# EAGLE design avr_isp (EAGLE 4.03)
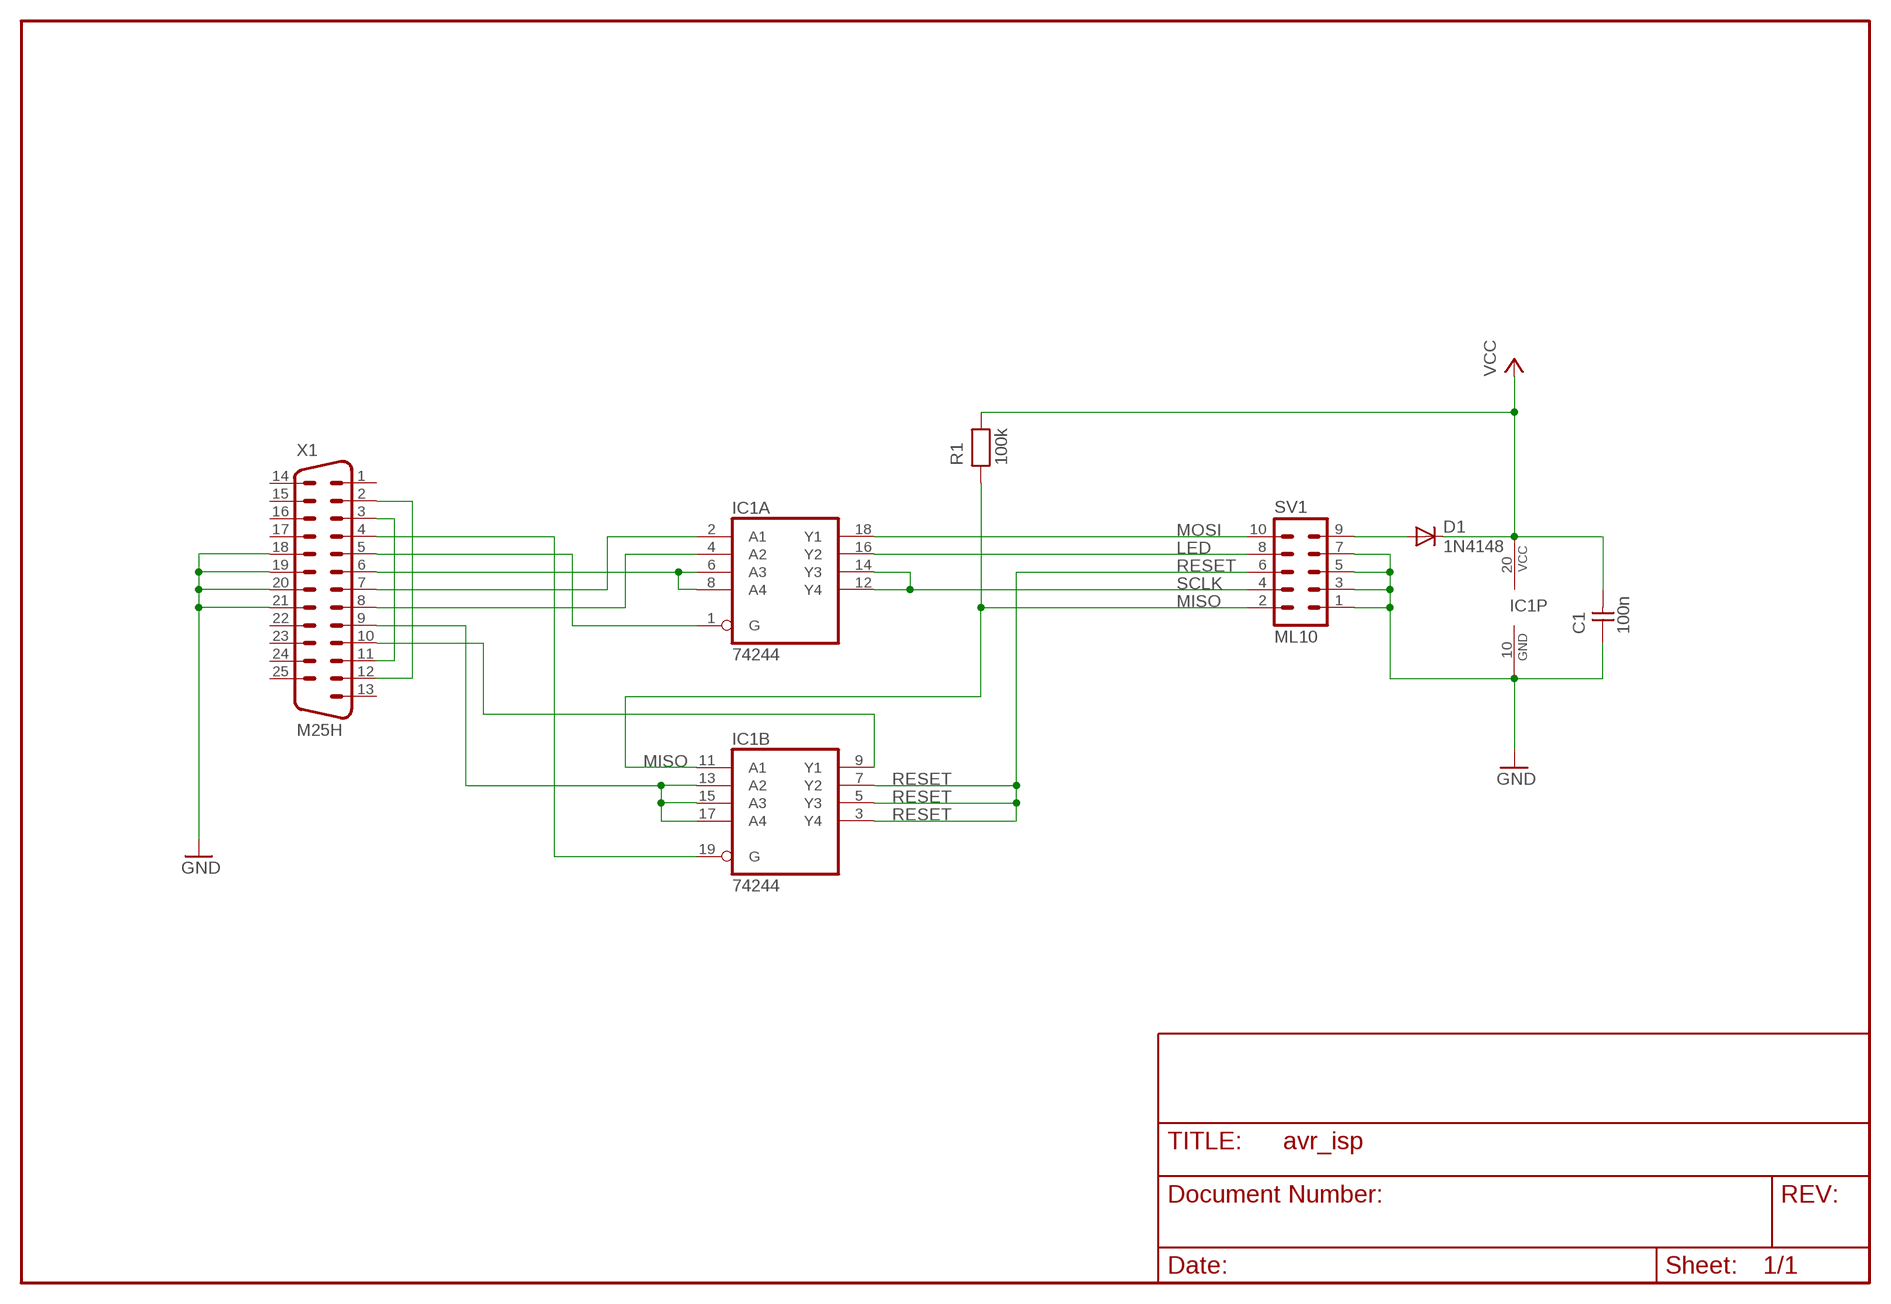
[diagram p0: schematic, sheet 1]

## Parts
C1  100n  CAPNP-2,5  [C-2,5]
D1  1N4148  [DO35-10]
IC1  74244  [DIL20]
R1  100k  RESEU-10  [R-10]
SV1  ML10  [ML10]
X1  M25H  [M25H]

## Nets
GND: C1.1 IC1.10(P:GND) SV1.1 SV1.3 SV1.5 SV1.7 X1.18 X1.19 X1.20 X1.21
LED: IC1.16(A:Y2) SV1.8
MISO: IC1.11(B:A1) R1.1 SV1.2
MOSI: IC1.18(A:Y1) SV1.10
N$5: IC1.1(A:G) X1.5
N$6: IC1.19(B:G) X1.4
N$7: IC1.2(A:A1) X1.7
N$8: IC1.4(A:A2) X1.8
N$9: X1.2 X1.12
N$10: X1.3 X1.11
N$12: IC1.9(B:Y1) X1.10
N$15: D1.A SV1.9
N$18: IC1.6(A:A3) IC1.8(A:A4) X1.6
N$20: IC1.13(B:A2) IC1.15(B:A3) IC1.17(B:A4) X1.9
RESET: IC1.3(B:Y4) IC1.5(B:Y3) IC1.7(B:Y2) SV1.6
SCLK: IC1.12(A:Y4) IC1.14(A:Y3) SV1.4
VCC: C1.2 D1.C IC1.20(P:VCC) R1.2
Unconnected: X1.1 X1.13 X1.14 X1.15 X1.16 X1.17 X1.22 X1.23 X1.24 X1.25

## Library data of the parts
C1 = discrete:CAPNP-2,5
D1 = diode:1N4148: DIODE
IC1 = 74xx:74244
R1 = discrete:RESEU-10
SV1 = con-ml:ML10: HARTING
X1 = subd:M25H

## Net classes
0 default: width 0.305 mm, clearance 0.406 mm

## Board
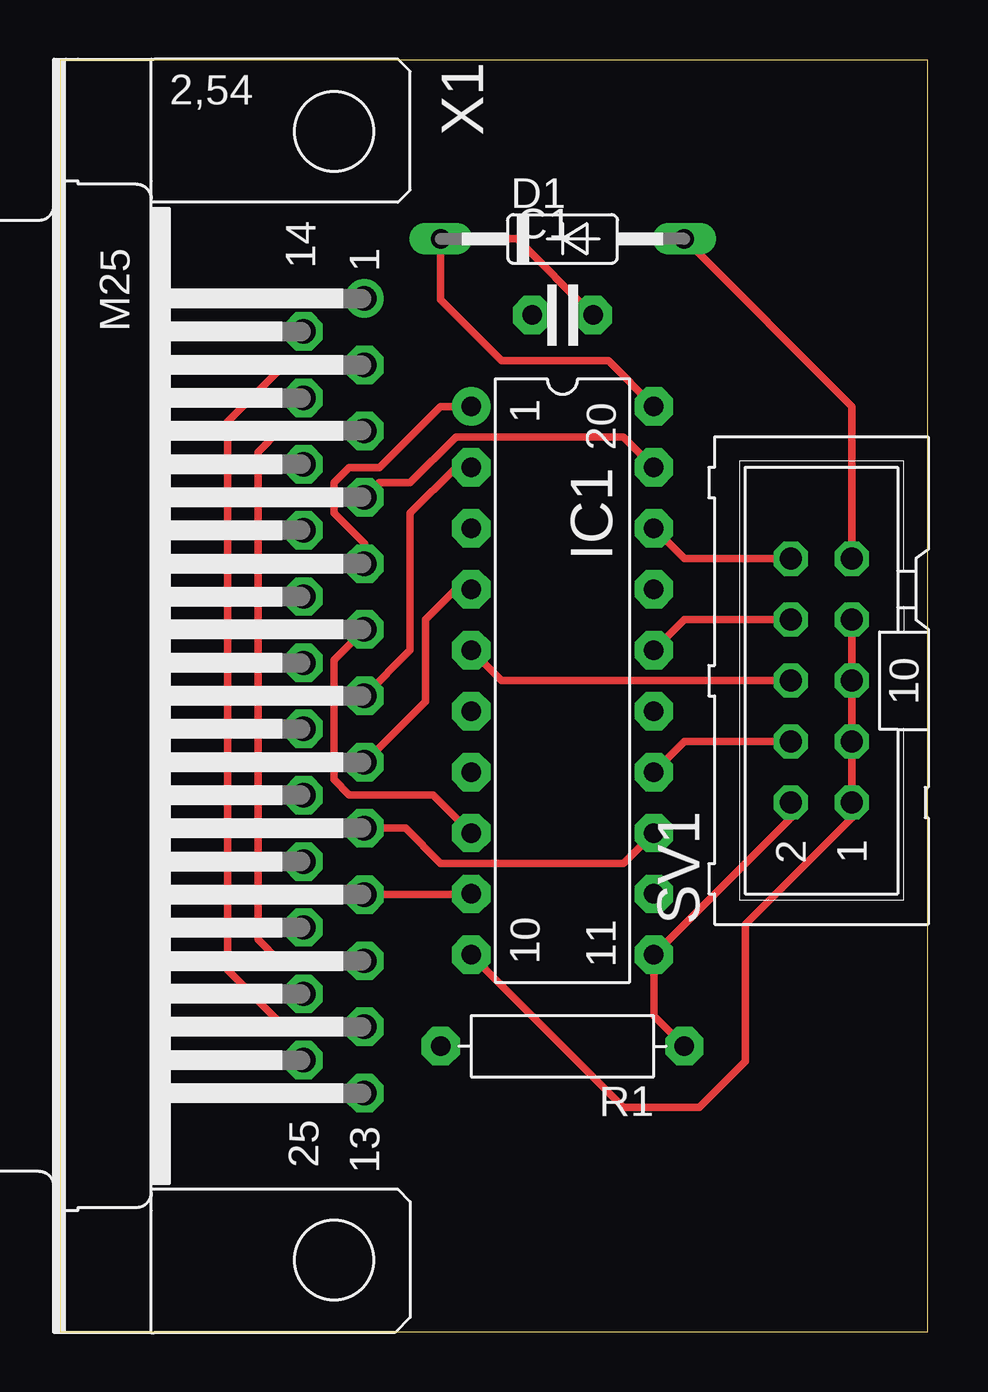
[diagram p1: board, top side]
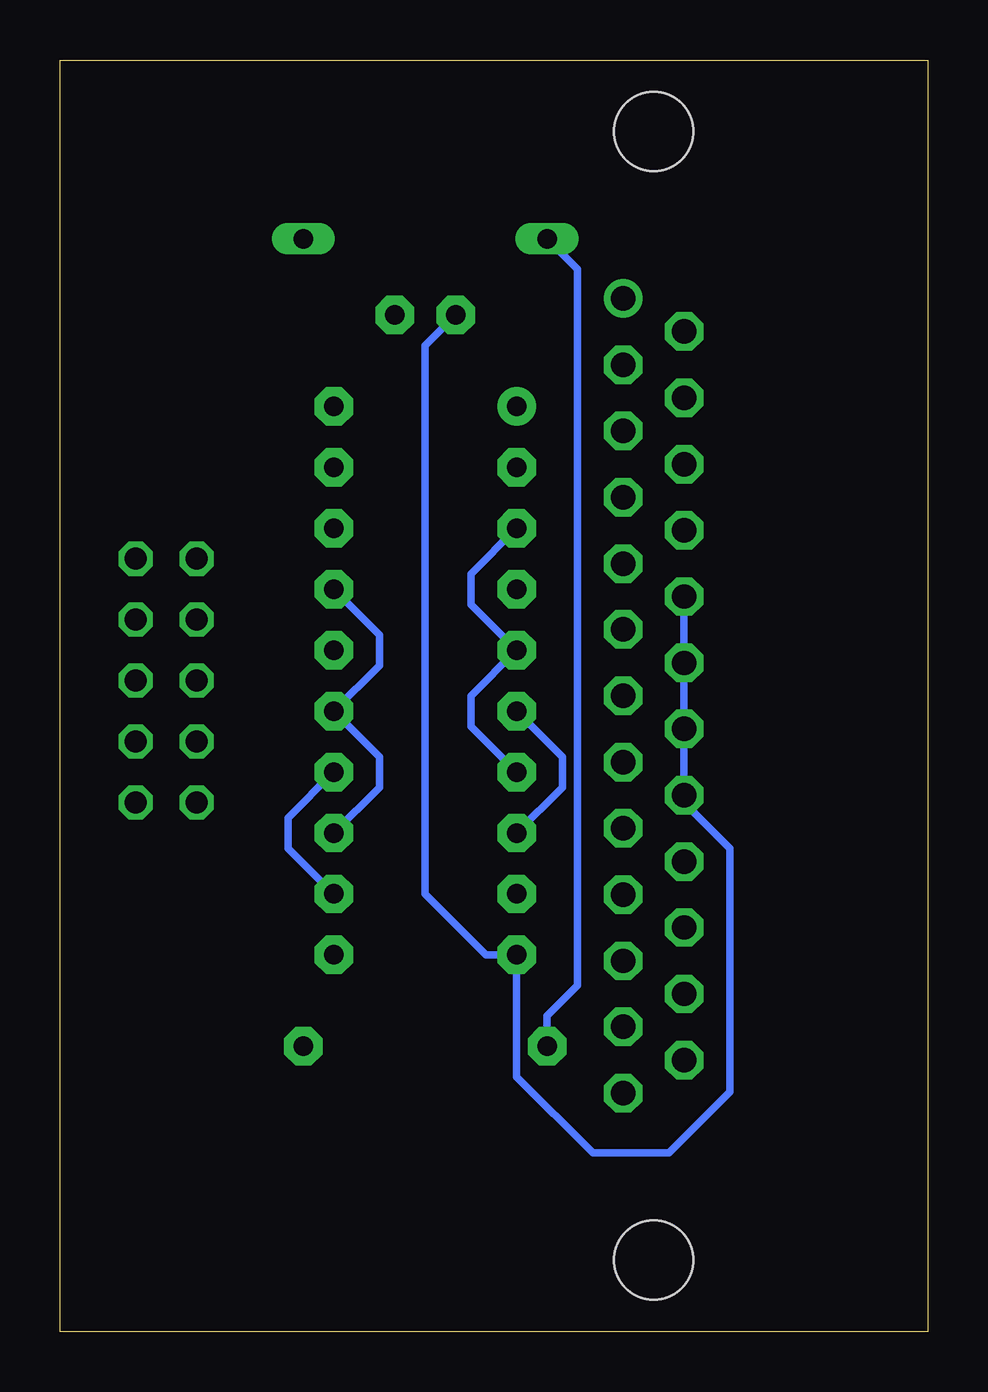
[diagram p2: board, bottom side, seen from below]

Size 36.18 x 53.01 mm. Coordinates in mm from the lower left corner, seen from the top.
Outline: 0,0 36.18,0 36.18,53.01 0,53.01 0,0
Copper layers used: Top, Bottom

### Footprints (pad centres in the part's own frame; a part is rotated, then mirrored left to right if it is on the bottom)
C-2,5 = drill 0.813 pad 1.6 octagon: 1 -1.27,0; 2 1.27,0
DO35-10 = drill 0.813 long: A 5.08,0; C -5.08,0
DIL20 = drill 0.813 pad 1.6 round: 1 -11.43,-3.81 | drill 0.813 pad 1.6 octagon: 2 -8.89,-3.81; 3 -6.35,-3.81; 4 -3.81,-3.81; 5 -1.27,-3.81; 6 1.27,-3.81; 7 3.81,-3.81; 8 6.35,-3.81; 9 8.89,-3.81; 10 11.43,-3.81; 11 11.43,3.81; 12 8.89,3.81; 13 6.35,3.81; 14 3.81,3.81; 15 1.27,3.81; 16 -1.27,3.81; 17 -3.81,3.81; 18 -6.35,3.81; 19 -8.89,3.81; 20 -11.43,3.81
R-10 = drill 0.813 pad 1.6 octagon: 1 -5.08,0; 2 5.08,0
ML10 = drill 0.914 octagon: 1 -5.08,-1.27; 2 -5.08,1.27; 3 -2.54,-1.27; 4 -2.54,1.27; 5 0,-1.27; 6 0,1.27; 7 2.54,-1.27; 8 2.54,1.27; 9 5.08,-1.27; 10 5.08,1.27
M25H = drill 1.016 pad 1.6 round: 1 -16.561,1.27 | drill 1.016 pad 1.6 octagon: 2 -13.792,1.27; 3 -11.049,1.27; 4 -8.28,1.27; 5 -5.512,1.27; 6 -2.769,1.27; 7 0,1.27; 8 2.769,1.27; 9 5.512,1.27; 10 8.28,1.27; 11 11.049,1.27; 12 13.792,1.27; 13 16.561,1.27; 14 -15.189,-1.27; 15 -12.421,-1.27; 16 -9.652,-1.27; 17 -6.909,-1.27; 18 -4.14,-1.27; 19 -1.372,-1.27; 20 1.372,-1.27; 21 4.14,-1.27; 22 6.909,-1.27; 23 9.652,-1.27; 24 12.421,-1.27; 25 15.189,-1.27 | hole 3.302: 23.52,0; -23.52,0

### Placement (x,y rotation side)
C1  20.95,42.38 0 top
D1  20.95,45.55 0 top
IC1  20.95,27.14 270 top
R1  20.95,11.9 180 top
SV1  31.74,27.14 90 top
X1  11.43,26.5 270 top

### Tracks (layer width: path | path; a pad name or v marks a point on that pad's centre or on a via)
GND
  Top 0.305: SV1.7 SV1.5 SV1.3 SV1.1 33.02,21.42 28.57,16.98 28.57,11.27 26.66,9.36 23.49,9.36 IC1.10
  Bottom 0.305: X1.19 10.16,27.77 | X1.20 10.16,24.6 | X1.20 X1.19 | X1.20 X1.21 10.16,22.06 8.25,20.15 8.25,10 10.79,7.46 13.97,7.46 17.14,10.63 IC1.10 18.41,15.71 20.95,18.25 20.95,41.11 C1.1 | X1.19 X1.18
LED
  Top 0.305: IC1.16 26.03,29.68 SV1.8
MISO
  Top 0.305: R1.1 24.76,13.17 IC1.11 30.47,21.42 SV1.2
MOSI
  Top 0.305: IC1.18 26.03,32.22 SV1.10
N$5
  Top 0.305: X1.5 12.7,32.85 11.43,34.12 11.43,35.39 12.06,36.03 13.33,36.03 15.87,38.57 IC1.1
N$6
  Top 0.305: X1.4 13.31,35.39 14.6,35.39 16.5,37.3 23.49,37.3 IC1.19
N$7
  Top 0.305: X1.7 14.6,28.41 14.6,34.12 16.5,36.03 IC1.2
N$8
  Top 0.305: X1.8 15.24,26.28 15.24,29.68 16.5,30.95 IC1.4
N$9
  Top 0.305: X1.12 9.34,12.71 6.98,15.08 6.98,37.94 9.34,40.3 X1.2
N$10
  Top 0.305: X1.11 9.14,15.46 8.25,16.34 8.25,36.66 9.14,37.55 X1.3
N$12
  Top 0.305: X1.10 17.11,18.22 IC1.9
N$15
  Top 0.305: SV1.9 33.02,38.57 D1.A
N$18
  Top 0.305: X1.6 11.43,28 11.43,23.01 12.06,22.38 15.55,22.38 IC1.8
  Bottom 0.305: IC1.8 15.24,22.7 15.24,23.96 IC1.6
N$20
  Top 0.305: X1.9 14.4,20.99 15.87,19.52 23.49,19.52 IC1.13
  Bottom 0.305: IC1.17 22.86,29.04 22.86,27.77 IC1.15 22.86,23.96 22.86,22.7 IC1.13
RESET
  Top 0.305: IC1.5 18.41,27.14 SV1.6
  Bottom 0.305: IC1.7 19.04,25.23 19.04,26.5 IC1.5 19.04,30.31 19.04,31.58 IC1.3
SCLK
  Top 0.305: IC1.14 26.03,24.6 SV1.4
  Bottom 0.305: IC1.14 26.66,21.42 26.66,20.15 IC1.12
VCC
  Top 0.305: IC1.20 22.86,40.48 18.41,40.48 15.87,43.02 D1.C 19.04,45.55 C1.2
  Bottom 0.305: R1.2 15.87,13.17 14.6,14.44 14.6,44.28 D1.C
